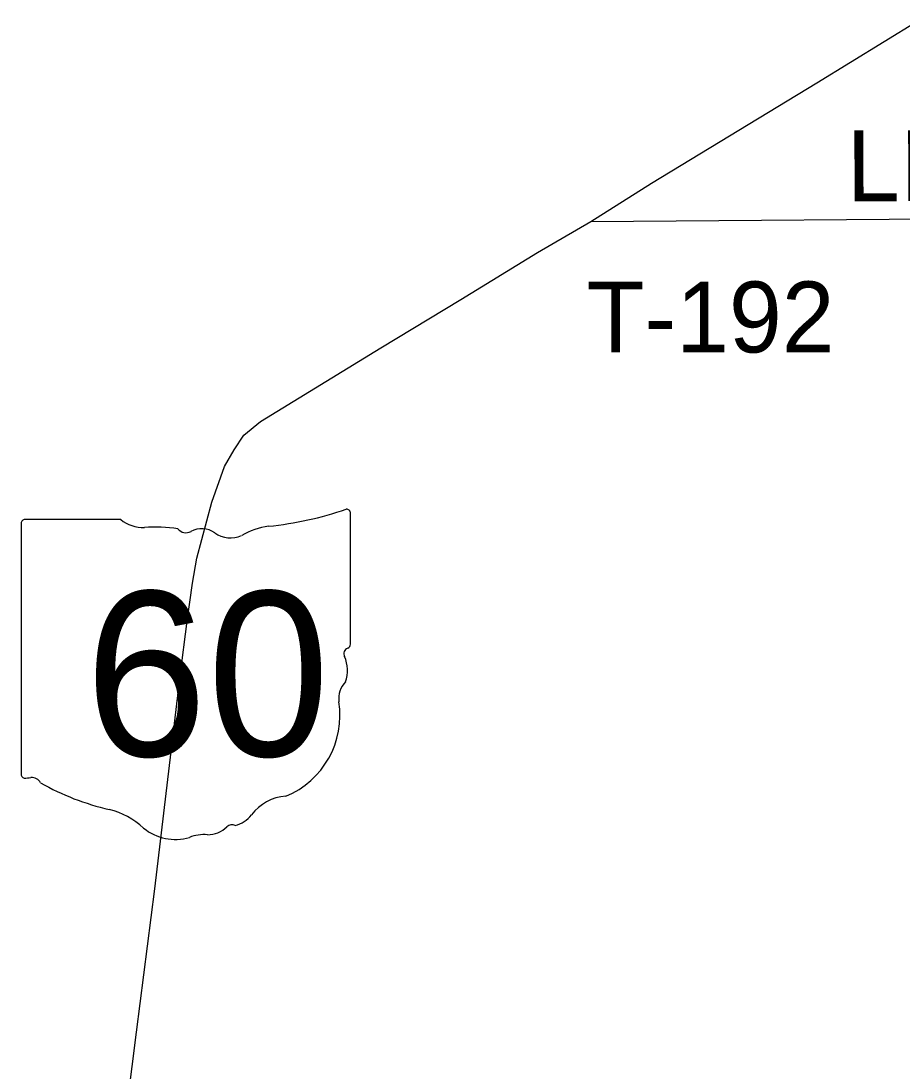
# Model space of a CAD drawing. Extents: x 0 to 34, y 0 to 22.
# Drawn here: x 4.119 to 4.825, y 19.221 to 20.062 of the extents above; entities that cross this region are included whole.
import ezdxf

# ---------------------------------------------------------------- set-up
doc = ezdxf.new("R2010")
doc.units = 0
for name, color, linetype in [('GM_X_State_Location', 7, 'Continuous'), ('GM_X_State_Route', 7, 'Continuous'), ('GM_X_State_Shield', 7, 'Continuous'), ('GM_X_Township_Road', 7, 'Continuous'), ('GM_X_Township_Road_Text', 7, 'Continuous')]:
    doc.layers.add(name, color=color, linetype=linetype)

msp = doc.modelspace()

# ---------------------------------------------------------------- linework, layer by layer
at = {"layer": 'GM_X_State_Route'}
msp.add_lwpolyline([(4.16982, 18.92667), (4.21105, 19.25237), (4.22575, 19.36708), (4.24593, 19.53793), (4.25163, 19.58158), (4.25579, 19.61207), (4.25927, 19.63207), (4.27132, 19.67688), (4.28131, 19.70545), (4.28911, 19.71886), (4.29681, 19.73072), (4.31019, 19.74147), (4.40647, 19.80047), (4.47074, 19.83929), (4.53215, 19.87702), (4.57466, 19.90173), (4.62339, 19.93251), (4.75565, 20.01278), (4.83658, 20.06235)], dxfattribs=at)
at = {"layer": 'GM_X_State_Shield'}
for p, q in [((4.38221, 19.56327), (4.38221, 19.66795)), ((4.11855, 19.65955), (4.11855, 19.45943)), ((4.19836, 19.66299), (4.12114, 19.66299)), ((4.38219, 19.56329), (4.38221, 19.56327))]:
    msp.add_line(p, q, dxfattribs=at)
for centre, radius, start, end in [((4.28829, 19.93582), 0.27962, 275.84447, 288.90645), ((4.37929, 19.66839), 0.00294, 351.86209, 97.738), ((4.12157, 19.65998), 0.00305, 98.1301, 188.1301), ((4.21675, 19.68622), 0.02963, 231.61951, 271.11188), ((4.22657, 19.55064), 0.10636, 80.48669, 94.98827), ((4.25072, 19.66101), 0.00855, 219.79206, 297.10237), ((4.26326, 19.63788), 0.01777, 54.46668, 119.14113), ((4.32396, 19.60187), 0.05625, 97.34618, 120.76885), ((4.2862, 19.66961), 0.02138, 233.85621, 294.82819), ((4.37908, 19.56286), 0.00314, 289.60381, 7.73413), ((4.38153, 19.55558), 0.00454, 107.94398, 210.33697), ((4.35264, 19.54235), 0.02727, 340.03296, 23.64957), ((4.39273, 19.51946), 0.01984, 136.8065, 186.92959), ((4.30395, 19.50614), 0.06994, 292.30889, 8.98584), ((4.12159, 19.45899), 0.00308, 171.95839, 258.30661), ((4.12206, 19.47946), 0.02352, 267.33899, 280.60386), ((4.12687, 19.44788), 0.00848, 29.74838, 93.27175), ((4.23393, 19.62768), 0.20192, 240.41292, 257.1985), ((4.33344, 19.40325), 0.0383, 94.40312, 142.57675), ((4.17373, 19.36952), 0.06318, 47.18416, 75.83597), ((4.28491, 19.44003), 0.0226, 282.87319, 323.27711), ((4.24206, 19.44689), 0.04009, 230.70037, 286.29184), ((4.26816, 19.4319), 0.02136, 268.77702, 315.54927), ((4.28748, 19.41252), 0.00601, 65.75173, 132.64842), ((4.26523, 19.3777), 0.03294, 85.69512, 111.20995)]:
    msp.add_arc(centre, radius, start, end, dxfattribs=at)
at = {"layer": 'GM_X_Township_Road'}
msp.add_lwpolyline([(4.57466, 19.90173), (4.9161, 19.90436), (5.27005, 19.90669), (5.67331, 19.90974), (5.95572, 19.91279), (6.16891, 19.9144), (6.59799, 19.91888), (6.99913, 19.92064)], dxfattribs=at)

# ---------------------------------------------------------------- texts
at = {"layer": 'GM_X_State_Location'}
for s, p in [('s', (4.24741, 19.54618)), ('r', (4.2474, 19.54618))]:
    msp.add_text(s, height=0.000189, dxfattribs=at).set_placement(p)
msp.add_text('60', height=0.000189, rotation=0.00001, dxfattribs=at).set_placement((4.19971, 19.53241))
at = {"layer": 'GM_X_State_Shield'}
msp.add_text('60', height=0.131836, dxfattribs=at).set_placement((4.16958, 19.47354))
at = {"layer": 'GM_X_Township_Road_Text'}
for s, rotation, p in [('LINCOLN', 0.31237, (4.77979, 19.91781)), ('T-192', 0.00001, (4.57138, 19.79684))]:
    msp.add_text(s, height=0.056818, rotation=rotation, dxfattribs=at).set_placement(p)

doc.saveas('drawing.dxf')
